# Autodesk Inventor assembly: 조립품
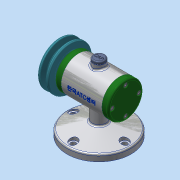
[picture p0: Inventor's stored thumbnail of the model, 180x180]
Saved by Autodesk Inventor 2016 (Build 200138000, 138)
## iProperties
Created: 2018-12
Part Number: 조립품
Material: 일반
Document SubType Name: Assembly
Designer: 605-03
Author: 605-03
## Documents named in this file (15)
- C:\Users\605-03\Desktop\481208V1016\조립품.iam
- C:\Users\605-03\Desktop\481208V1016\V벨트풀리.ipt
- C:\Users\605-03\Desktop\481208V1016\고무캡.ipt
- C:\Users\605-03\Desktop\481208V1016\너트 M8.ipt
- 너트 M8.ipt
- C:\Users\605-03\Desktop\481208V1016\뒤커버.ipt
- C:\Users\605-03\Desktop\481208V1016\베어링 15 x 32 x 9.ipt
- C:\Users\605-03\Desktop\481208V1016\본체.ipt
- C:\Users\605-03\Desktop\481208V1016\볼트 M4 x 12.ipt
- C:\Users\605-03\Desktop\481208V1016\스프링와셔 8.ipt
- C:\Users\605-03\Desktop\481208V1016\앞커버.ipt
- C:\Users\605-03\Desktop\481208V1016\오일 실 15 25 7.ipt
- C:\Users\605-03\Desktop\481208V1016\와셔 8x17.ipt
- C:\Users\605-03\Desktop\481208V1016\축.ipt
- C:\Users\605-03\Desktop\481208V1016\키 3 x 3 x 12.ipt
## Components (2 placed, 2 different names)
1. V벨트풀리:2 — 각도:1
2. 고무캡:2
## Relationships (1: Angle 1)
- 각도:1 [Angle]: V벨트풀리:2
